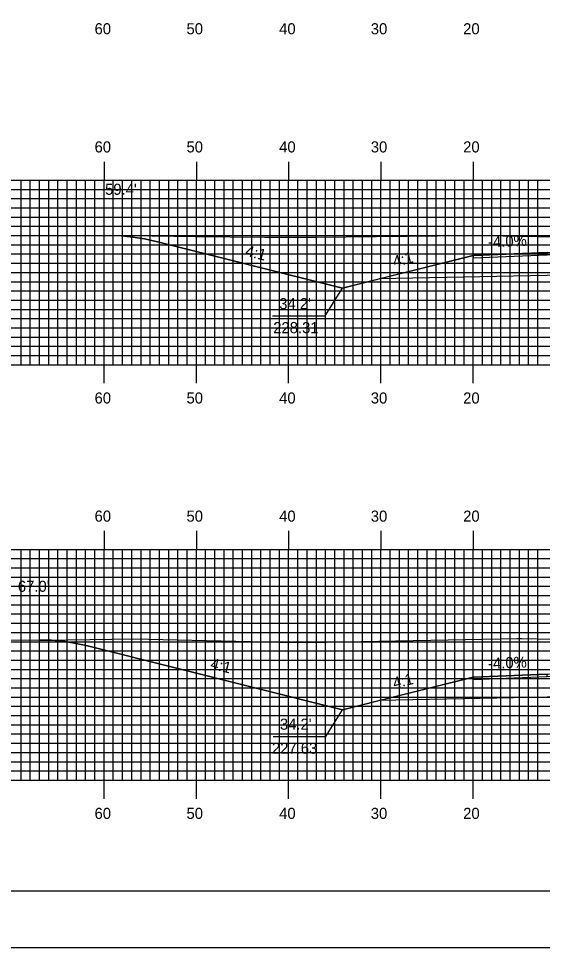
# Model space of a CAD drawing. Extents: x 1803110 to 1803453, y 442591 to 442811.
# Drawn here: x 1803206.4 to 1803263.1, y 442590.5 to 442691.2 of the extents above; entities that cross this region are included whole.
import ezdxf

# ---------------------------------------------------------------- set-up
doc = ezdxf.new("R2010")
doc.units = 0
for name, color, linetype in [('ANNOTATION', 7, 'Continuous'), ('BORDER', 7, 'Continuous'), ('D_Roadway_Centerline', 7, 'Continuous'), ('D_Roadway_Edge_Shoulder', 7, 'Continuous'), ('D_Roadway_SlopeLines', 7, 'Continuous'), ('D_Roadway_SubGrade', 7, 'Continuous'), ('D_Text_Standard', 7, 'Continuous'), ('H_V ANNOTATION', 7, 'Continuous'), ('MAJOR', 7, 'Continuous'), ('MINOR', 7, 'Continuous'), ('PLOT BOUNDARY', 7, 'Continuous'), ('S_Roadway_Centerline', 7, 'Continuous')]:
    doc.layers.add(name, color=color, linetype=linetype)

msp = doc.modelspace()

# ---------------------------------------------------------------- linework, layer by layer
at = {"layer": 'ANNOTATION'}
for points in [[(1803233.88, 442658.97), (1803239.57, 442658.97), (1803241.45, 442661.97)], [(1803233.95, 442613.4), (1803239.64, 442613.4), (1803241.45, 442616.3)]]:
    msp.add_lwpolyline(points, dxfattribs=at)
at = {"layer": 'BORDER'}
msp.add_lwpolyline([(1803126.03, 442596.67), (1803446.03, 442596.67), (1803446.03, 442806.67), (1803126.03, 442806.67)], close=True, dxfattribs=at)
at = {"layer": 'D_Roadway_Centerline'}
for points in [[(1803216.26, 442667.67), (1803217.51, 442667.62), (1803218.76, 442667.5), (1803220.01, 442667.3), (1803221.26, 442667.02), (1803241.45, 442661.97), (1803245.45, 442662.97), (1803255.63, 442665.52), (1803263.63, 442665.84), (1803275.63, 442666.08), (1803287.63, 442665.84), (1803295.63, 442665.52), (1803305.8, 442662.97), (1803309.8, 442661.97), (1803328.09, 442666.55), (1803329.34, 442666.83), (1803330.59, 442667.04), (1803331.84, 442667.19), (1803333.09, 442667.27)], [(1803208.67, 442623.85), (1803209.92, 442623.82), (1803211.17, 442623.71), (1803212.42, 442623.52), (1803213.67, 442623.24), (1803241.45, 442616.3), (1803245.45, 442617.3), (1803255.63, 442619.84), (1803263.63, 442620.16), (1803275.63, 442620.4), (1803287.63, 442620.16), (1803295.63, 442619.84), (1803305.8, 442617.3), (1803309.8, 442616.3), (1803335.24, 442622.66), (1803336.49, 442622.93), (1803337.74, 442623.13), (1803338.99, 442623.24), (1803340.24, 442623.28)]]:
    msp.add_lwpolyline(points, dxfattribs=at)
at = {"layer": 'D_Roadway_Edge_Shoulder'}
for points in [[(1803263.63, 442665.84), (1803255.63, 442665.52), (1803255.63, 442665.27), (1803263.63, 442665.59)], [(1803263.63, 442620.16), (1803255.63, 442619.84), (1803255.63, 442619.59), (1803263.63, 442619.91)]]:
    msp.add_lwpolyline(points, close=True, dxfattribs=at)
at = {"layer": 'D_Roadway_SlopeLines'}
for points in [[(1803241.45, 442661.97), (1803221.26, 442667.02), (1803220.01, 442667.3), (1803218.76, 442667.5), (1803217.51, 442667.62), (1803216.26, 442667.67)], [(1803255.63, 442665.52), (1803241.45, 442661.97)], [(1803241.45, 442616.3), (1803213.67, 442623.24), (1803212.42, 442623.52), (1803211.17, 442623.71), (1803209.92, 442623.82), (1803208.67, 442623.85)], [(1803255.63, 442619.84), (1803241.45, 442616.3)]]:
    msp.add_lwpolyline(points, dxfattribs=at)
at = {"layer": 'D_Roadway_SubGrade'}
for points in [[(1803263.63, 442663.34), (1803245.45, 442662.97), (1803255.63, 442665.52), (1803255.63, 442665.27), (1803263.63, 442665.59), (1803275.63, 442665.83), (1803287.63, 442665.59), (1803295.63, 442665.27), (1803295.63, 442665.52), (1803305.8, 442662.97), (1803287.63, 442663.34), (1803275.63, 442663.58)], [(1803263.63, 442617.66), (1803245.45, 442617.3), (1803255.63, 442619.84), (1803255.63, 442619.59), (1803263.63, 442619.91), (1803275.63, 442620.15), (1803287.63, 442619.91), (1803295.63, 442619.59), (1803295.63, 442619.84), (1803305.8, 442617.3), (1803287.63, 442617.66), (1803275.63, 442617.9)]]:
    msp.add_lwpolyline(points, close=True, dxfattribs=at)
at = {"layer": 'MAJOR'}
for p, q in [((1803215.63, 442675.67), (1803215.63, 442673.67)), ((1803225.63, 442675.67), (1803225.63, 442673.67)), ((1803235.63, 442675.67), (1803235.63, 442673.67)), ((1803245.63, 442675.67), (1803245.63, 442673.67)), ((1803255.63, 442675.67), (1803255.63, 442673.67)), ((1803135.63, 442673.67), (1803415.63, 442673.67)), ((1803135.63, 442673.67), (1803415.63, 442673.67)), ((1803215.63, 442653.67), (1803215.63, 442673.67)), ((1803225.63, 442653.67), (1803225.63, 442673.67)), ((1803235.63, 442653.67), (1803235.63, 442673.67)), ((1803245.63, 442653.67), (1803245.63, 442673.67)), ((1803255.63, 442653.67), (1803255.63, 442673.67)), ((1803135.63, 442668.67), (1803415.63, 442668.67)), ((1803135.63, 442663.67), (1803415.63, 442663.67)), ((1803135.63, 442658.67), (1803415.63, 442658.67)), ((1803135.63, 442653.67), (1803415.63, 442653.67)), ((1803135.63, 442653.67), (1803415.63, 442653.67)), ((1803215.63, 442651.66), (1803215.63, 442653.67)), ((1803225.63, 442651.66), (1803225.63, 442653.67)), ((1803235.63, 442651.66), (1803235.63, 442653.67)), ((1803245.63, 442651.66), (1803245.63, 442653.67)), ((1803255.63, 442651.66), (1803255.63, 442653.67)), ((1803215.63, 442635.67), (1803215.63, 442633.67)), ((1803225.63, 442635.67), (1803225.63, 442633.67)), ((1803235.63, 442635.67), (1803235.63, 442633.67)), ((1803245.63, 442635.67), (1803245.63, 442633.67)), ((1803255.63, 442635.67), (1803255.63, 442633.67)), ((1803135.63, 442633.67), (1803415.63, 442633.67)), ((1803135.63, 442633.67), (1803415.63, 442633.67)), ((1803215.63, 442608.67), (1803215.63, 442633.67)), ((1803225.63, 442608.67), (1803225.63, 442633.67)), ((1803235.63, 442608.67), (1803235.63, 442633.67)), ((1803245.63, 442608.67), (1803245.63, 442633.67)), ((1803255.63, 442608.67), (1803255.63, 442633.67)), ((1803135.63, 442628.67), (1803415.63, 442628.67)), ((1803135.63, 442623.67), (1803415.63, 442623.67)), ((1803135.63, 442618.67), (1803415.63, 442618.67)), ((1803135.63, 442613.67), (1803415.63, 442613.67)), ((1803135.63, 442608.67), (1803415.63, 442608.67)), ((1803135.63, 442608.67), (1803415.63, 442608.67)), ((1803215.63, 442606.66), (1803215.63, 442608.67)), ((1803225.63, 442606.66), (1803225.63, 442608.67)), ((1803235.63, 442606.66), (1803235.63, 442608.67)), ((1803245.63, 442606.66), (1803245.63, 442608.67)), ((1803255.63, 442606.66), (1803255.63, 442608.67))]:
    msp.add_line(p, q, dxfattribs=at)
at = {"layer": 'MINOR'}
for p, q in [((1803206.63, 442653.67), (1803206.63, 442673.67)), ((1803207.63, 442653.67), (1803207.63, 442673.67)), ((1803208.63, 442653.67), (1803208.63, 442673.67)), ((1803209.63, 442653.67), (1803209.63, 442673.67)), ((1803210.63, 442653.67), (1803210.63, 442673.67)), ((1803211.63, 442653.67), (1803211.63, 442673.67)), ((1803212.63, 442653.67), (1803212.63, 442673.67)), ((1803213.63, 442653.67), (1803213.63, 442673.67)), ((1803214.63, 442653.67), (1803214.63, 442673.67)), ((1803216.63, 442653.67), (1803216.63, 442673.67)), ((1803217.63, 442653.67), (1803217.63, 442673.67)), ((1803218.63, 442653.67), (1803218.63, 442673.67)), ((1803219.63, 442653.67), (1803219.63, 442673.67)), ((1803220.63, 442653.67), (1803220.63, 442673.67)), ((1803221.63, 442653.67), (1803221.63, 442673.67)), ((1803222.63, 442653.67), (1803222.63, 442673.67)), ((1803223.63, 442653.67), (1803223.63, 442673.67)), ((1803224.63, 442653.67), (1803224.63, 442673.67)), ((1803226.63, 442653.67), (1803226.63, 442673.67)), ((1803227.63, 442653.67), (1803227.63, 442673.67)), ((1803228.63, 442653.67), (1803228.63, 442673.67)), ((1803229.63, 442653.67), (1803229.63, 442673.67)), ((1803230.63, 442653.67), (1803230.63, 442673.67)), ((1803231.63, 442653.67), (1803231.63, 442673.67)), ((1803232.63, 442653.67), (1803232.63, 442673.67)), ((1803233.63, 442653.67), (1803233.63, 442673.67)), ((1803234.63, 442653.67), (1803234.63, 442673.67)), ((1803236.63, 442653.67), (1803236.63, 442673.67)), ((1803237.63, 442653.67), (1803237.63, 442673.67)), ((1803238.63, 442653.67), (1803238.63, 442673.67)), ((1803239.63, 442653.67), (1803239.63, 442673.67)), ((1803240.63, 442653.67), (1803240.63, 442673.67)), ((1803241.63, 442653.67), (1803241.63, 442673.67)), ((1803242.63, 442653.67), (1803242.63, 442673.67)), ((1803243.63, 442653.67), (1803243.63, 442673.67)), ((1803244.63, 442653.67), (1803244.63, 442673.67)), ((1803246.63, 442653.67), (1803246.63, 442673.67)), ((1803247.63, 442653.67), (1803247.63, 442673.67)), ((1803248.63, 442653.67), (1803248.63, 442673.67)), ((1803249.63, 442653.67), (1803249.63, 442673.67)), ((1803250.63, 442653.67), (1803250.63, 442673.67)), ((1803251.63, 442653.67), (1803251.63, 442673.67)), ((1803252.63, 442653.67), (1803252.63, 442673.67)), ((1803253.63, 442653.67), (1803253.63, 442673.67)), ((1803254.63, 442653.67), (1803254.63, 442673.67)), ((1803256.63, 442653.67), (1803256.63, 442673.67)), ((1803257.63, 442653.67), (1803257.63, 442673.67)), ((1803258.63, 442653.67), (1803258.63, 442673.67)), ((1803259.63, 442653.67), (1803259.63, 442673.67)), ((1803260.63, 442653.67), (1803260.63, 442673.67)), ((1803261.63, 442653.67), (1803261.63, 442673.67)), ((1803262.63, 442653.67), (1803262.63, 442673.67)), ((1803135.63, 442672.67), (1803415.63, 442672.67)), ((1803135.63, 442671.67), (1803415.63, 442671.67)), ((1803135.63, 442670.67), (1803415.63, 442670.67)), ((1803135.63, 442669.67), (1803415.63, 442669.67)), ((1803135.63, 442667.67), (1803415.63, 442667.67)), ((1803135.63, 442666.67), (1803415.63, 442666.67)), ((1803135.63, 442665.67), (1803415.63, 442665.67)), ((1803135.63, 442664.67), (1803415.63, 442664.67)), ((1803135.63, 442662.67), (1803415.63, 442662.67)), ((1803135.63, 442661.67), (1803415.63, 442661.67)), ((1803135.63, 442660.67), (1803415.63, 442660.67)), ((1803135.63, 442659.67), (1803415.63, 442659.67)), ((1803135.63, 442657.67), (1803415.63, 442657.67)), ((1803135.63, 442656.67), (1803415.63, 442656.67)), ((1803135.63, 442655.67), (1803415.63, 442655.67)), ((1803135.63, 442654.67), (1803415.63, 442654.67)), ((1803206.63, 442608.67), (1803206.63, 442633.67)), ((1803207.63, 442608.67), (1803207.63, 442633.67)), ((1803208.63, 442608.67), (1803208.63, 442633.67)), ((1803209.63, 442608.67), (1803209.63, 442633.67)), ((1803210.63, 442608.67), (1803210.63, 442633.67)), ((1803211.63, 442608.67), (1803211.63, 442633.67)), ((1803212.63, 442608.67), (1803212.63, 442633.67)), ((1803213.63, 442608.67), (1803213.63, 442633.67)), ((1803214.63, 442608.67), (1803214.63, 442633.67)), ((1803216.63, 442608.67), (1803216.63, 442633.67)), ((1803217.63, 442608.67), (1803217.63, 442633.67)), ((1803218.63, 442608.67), (1803218.63, 442633.67)), ((1803219.63, 442608.67), (1803219.63, 442633.67)), ((1803220.63, 442608.67), (1803220.63, 442633.67)), ((1803221.63, 442608.67), (1803221.63, 442633.67)), ((1803222.63, 442608.67), (1803222.63, 442633.67)), ((1803223.63, 442608.67), (1803223.63, 442633.67)), ((1803224.63, 442608.67), (1803224.63, 442633.67)), ((1803226.63, 442608.67), (1803226.63, 442633.67)), ((1803227.63, 442608.67), (1803227.63, 442633.67)), ((1803228.63, 442608.67), (1803228.63, 442633.67)), ((1803229.63, 442608.67), (1803229.63, 442633.67)), ((1803230.63, 442608.67), (1803230.63, 442633.67)), ((1803231.63, 442608.67), (1803231.63, 442633.67)), ((1803232.63, 442608.67), (1803232.63, 442633.67)), ((1803233.63, 442608.67), (1803233.63, 442633.67)), ((1803234.63, 442608.67), (1803234.63, 442633.67)), ((1803236.63, 442608.67), (1803236.63, 442633.67)), ((1803237.63, 442608.67), (1803237.63, 442633.67)), ((1803238.63, 442608.67), (1803238.63, 442633.67)), ((1803239.63, 442608.67), (1803239.63, 442633.67)), ((1803240.63, 442608.67), (1803240.63, 442633.67)), ((1803241.63, 442608.67), (1803241.63, 442633.67)), ((1803242.63, 442608.67), (1803242.63, 442633.67)), ((1803243.63, 442608.67), (1803243.63, 442633.67)), ((1803244.63, 442608.67), (1803244.63, 442633.67)), ((1803246.63, 442608.67), (1803246.63, 442633.67)), ((1803247.63, 442608.67), (1803247.63, 442633.67)), ((1803248.63, 442608.67), (1803248.63, 442633.67)), ((1803249.63, 442608.67), (1803249.63, 442633.67)), ((1803250.63, 442608.67), (1803250.63, 442633.67)), ((1803251.63, 442608.67), (1803251.63, 442633.67)), ((1803252.63, 442608.67), (1803252.63, 442633.67)), ((1803253.63, 442608.67), (1803253.63, 442633.67)), ((1803254.63, 442608.67), (1803254.63, 442633.67)), ((1803256.63, 442608.67), (1803256.63, 442633.67)), ((1803257.63, 442608.67), (1803257.63, 442633.67)), ((1803258.63, 442608.67), (1803258.63, 442633.67)), ((1803259.63, 442608.67), (1803259.63, 442633.67)), ((1803260.63, 442608.67), (1803260.63, 442633.67)), ((1803261.63, 442608.67), (1803261.63, 442633.67)), ((1803262.63, 442608.67), (1803262.63, 442633.67)), ((1803135.63, 442632.67), (1803415.63, 442632.67)), ((1803135.63, 442631.67), (1803415.63, 442631.67)), ((1803135.63, 442630.67), (1803415.63, 442630.67)), ((1803135.63, 442629.67), (1803415.63, 442629.67)), ((1803135.63, 442627.67), (1803415.63, 442627.67)), ((1803135.63, 442626.67), (1803415.63, 442626.67)), ((1803135.63, 442625.67), (1803415.63, 442625.67)), ((1803135.63, 442624.67), (1803415.63, 442624.67)), ((1803135.63, 442622.67), (1803415.63, 442622.67)), ((1803135.63, 442621.67), (1803415.63, 442621.67)), ((1803135.63, 442620.67), (1803415.63, 442620.67)), ((1803135.63, 442619.67), (1803415.63, 442619.67)), ((1803135.63, 442617.67), (1803415.63, 442617.67)), ((1803135.63, 442616.67), (1803415.63, 442616.67)), ((1803135.63, 442615.67), (1803415.63, 442615.67)), ((1803135.63, 442614.67), (1803415.63, 442614.67)), ((1803135.63, 442612.67), (1803415.63, 442612.67)), ((1803135.63, 442611.67), (1803415.63, 442611.67)), ((1803135.63, 442610.67), (1803415.63, 442610.67)), ((1803135.63, 442609.67), (1803415.63, 442609.67))]:
    msp.add_line(p, q, dxfattribs=at)
at = {"layer": 'PLOT BOUNDARY'}
msp.add_lwpolyline([(1803109.84, 442590.55), (1803449.84, 442590.55), (1803449.84, 442810.55), (1803109.84, 442810.55)], close=True, dxfattribs=at)
at = {"layer": 'S_Roadway_Centerline'}
for points in [[(1803200.7, 442667.63), (1803217.19, 442667.67), (1803220.81, 442667.62), (1803225.55, 442667.56), (1803233.02, 442667.5), (1803238.55, 442667.5), (1803251.74, 442667.64), (1803255.42, 442667.71), (1803258.86, 442667.64), (1803268.38, 442667.44), (1803277.59, 442666.86), (1803280.77, 442666.87), (1803291.21, 442667.42), (1803301.67, 442667.52), (1803323.83, 442667.05), (1803326.31, 442666.97), (1803329.6, 442667.13), (1803331.57, 442667.21), (1803337.63, 442667.46)], [(1803203.03, 442623.87), (1803209.31, 442623.84), (1803218.86, 442623.97), (1803234.63, 442623.63), (1803239.72, 442623.61), (1803260.41, 442624.01), (1803260.67, 442624), (1803260.89, 442624), (1803272.73, 442623.75), (1803281.53, 442623.59), (1803286.63, 442623.44), (1803296.14, 442623.39), (1803304.1, 442623.38), (1803308.16, 442623.38), (1803312.1, 442623.56), (1803325.5, 442623.51), (1803338.02, 442623.28)]]:
    msp.add_lwpolyline(points, dxfattribs=at)

# ---------------------------------------------------------------- texts
at = {"layer": 'ANNOTATION'}
for s, rotation, p in [('-4.0%', 2.2906, (1803257.26, 442666.38)), ('4:1', 345.9638, (1803230.86, 442665.48)), ('4:1', 14.0362, (1803247.08, 442664.24)), ('4:1', 345.9638, (1803227.07, 442620.76)), ('-4.0%', 2.2906, (1803257.26, 442620.71)), ('4:1', 14.0362, (1803247.08, 442618.57))]:
    msp.add_text(s, height=1.2, rotation=rotation, dxfattribs=at).set_placement(p)
for s, p in [("34.2'", (1803234.61, 442659.69)), ('228.31', (1803233.96, 442657.09)), ("34.2'", (1803234.68, 442614.13)), ('227.63', (1803233.82, 442611.53))]:
    msp.add_text(s, height=1.2, dxfattribs=at).set_placement(p)
at = {"layer": 'D_Text_Standard'}
for s, p in [("59.4'", (1803215.74, 442672.08)), ("67.0'", (1803206.29, 442629.07))]:
    msp.add_text(s, height=1.2, dxfattribs=at).set_placement(p)
at = {"layer": 'H_V ANNOTATION'}
for s, p in [('60', (1803214.6, 442689.47)), ('50', (1803224.56, 442689.47)), ('40', (1803234.6, 442689.47)), ('30', (1803244.53, 442689.47)), ('20', (1803254.54, 442689.47)), ('60', (1803214.6, 442676.67)), ('50', (1803224.56, 442676.67)), ('40', (1803234.6, 442676.67)), ('30', (1803244.53, 442676.67)), ('20', (1803254.54, 442676.67)), ('60', (1803214.6, 442649.47)), ('50', (1803224.56, 442649.47)), ('40', (1803234.6, 442649.47)), ('30', (1803244.53, 442649.47)), ('20', (1803254.54, 442649.47)), ('60', (1803214.6, 442636.67)), ('50', (1803224.56, 442636.67)), ('40', (1803234.6, 442636.67)), ('30', (1803244.53, 442636.67)), ('20', (1803254.54, 442636.67)), ('60', (1803214.6, 442604.47)), ('50', (1803224.56, 442604.47)), ('40', (1803234.6, 442604.47)), ('30', (1803244.53, 442604.47)), ('20', (1803254.54, 442604.47))]:
    msp.add_text(s, height=1.2, dxfattribs=at).set_placement(p)

doc.saveas('drawing.dxf')
